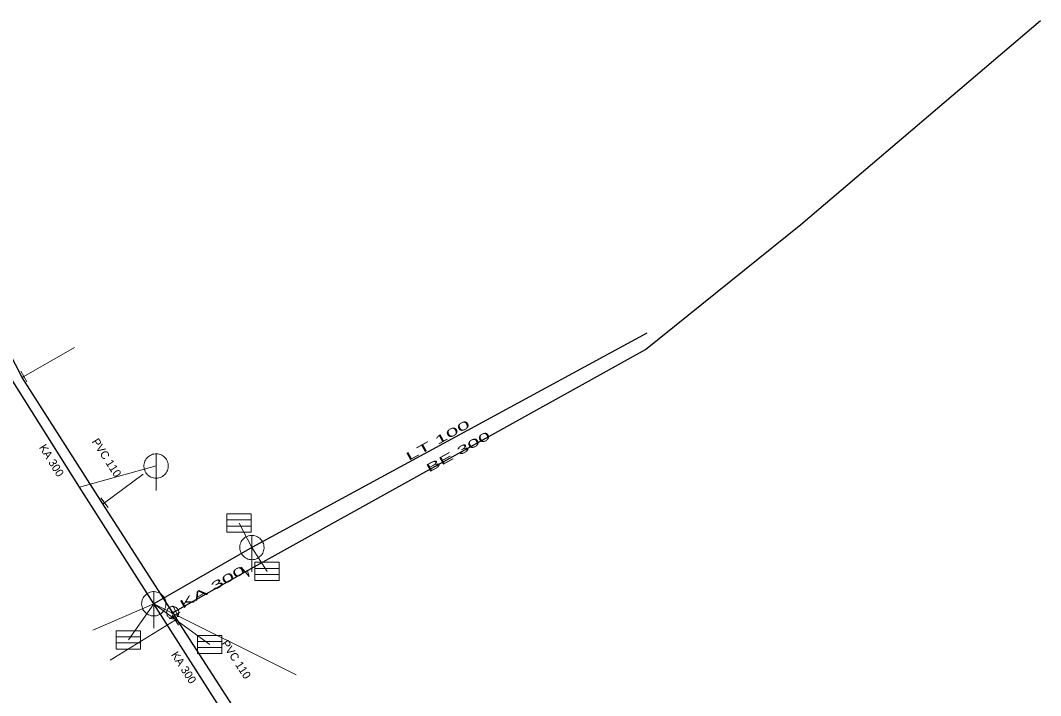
# Model space of a CAD drawing. Extents: x -688296 to -687852, y -973332 to -972816.
# Drawn here: x -687935.8 to -687852, y -973112.8 to -973057.3 of the extents above; entities that cross this region are included whole.
import ezdxf
from ezdxf.enums import TextEntityAlignment as Align

# ---------------------------------------------------------------- set-up
doc = ezdxf.new("R2010")
doc.units = 0
doc.header["$LTSCALE"] = 0.27
for name, color, linetype, lineweight in [('1', 7, 'Continuous', 25), ('11', 7, 'Continuous', 13), ('13', 7, 'Continuous', 13), ('14', 7, 'Continuous', 13), ('17', 7, 'Continuous', 25), ('22', 7, 'Continuous', 13), ('34', 7, 'Continuous', 13), ('47', 7, 'Continuous', 13)]:
    doc.layers.add(name, color=color, linetype=linetype, lineweight=lineweight)

msp = doc.modelspace()

# ---------------------------------------------------------------- linework, layer by layer
at = {"layer": '11'}
for p, q in [((-687924.64, -973093.94), (-687930.94, -973095.67)), ((-687917.83, -973098.63), (-687916.78, -973100.64)), ((-687915.53, -973102.61), (-687916.78, -973100.64)), ((-687929.84, -973107.42), (-687924.829, -973105.26)), ((-687926.92, -973108.23), (-687924.829, -973105.26)), ((-687920.239, -973108.609), (-687924.829, -973105.26)), ((-687913.14, -973111.1), (-687924.829, -973105.26))]:
    msp.add_line(p, q, dxfattribs=at)
at = {"layer": '13'}
for p, q in [((-687935.509, -973086.585), (-687931.329, -973084.21)), ((-687928.878, -973096.96), (-687925.69, -973094.62)), ((-687923.067, -973106.599), (-687928.399, -973109.899))]:
    msp.add_line(p, q, dxfattribs=at)
at = {"layer": '14', "lineweight": 25}
for p, q in [((-687884.357, -973083.031), (-687916.78, -973100.64)), ((-687916.78, -973100.64), (-687924.829, -973105.26)), ((-687916.609, -973118.16), (-687924.829, -973105.26))]:
    msp.add_line(p, q, dxfattribs=at)
at = {"layer": '14'}
for p, q in [((-687935.64, -973086.66), (-687935.509, -973086.585)), ((-687929, -973097.05), (-687928.878, -973096.96)), ((-687922.94, -973106.52), (-687923.067, -973106.599))]:
    msp.add_line(p, q, dxfattribs=at)
at = {"layer": '14', "lineweight": 25}
msp.add_lwpolyline([(-687924.829, -973105.26), (-687930.94, -973095.67), (-687938.239, -973084.09)], dxfattribs=at)
at = {"layer": '14'}
msp.add_lwpolyline([(-687923.129, -973106.219), (-687923.279, -973105.989), (-687923.039, -973105.87)], dxfattribs=at)
at = {"layer": '17'}
msp.add_line((-687923.039, -973105.87), (-687917.319, -973102.639), dxfattribs=at)
for points in [[(-687917.319, -973102.639), (-687884.48, -973084.37), (-687871.73, -973074.109), (-687852.039, -973057.339)], [(-687923.279, -973105.989), (-687929, -973097.05), (-687935.64, -973086.66), (-687936.739, -973084.53), (-687942.199, -973073.68), (-687943.129, -973071.829)], [(-687914.539, -973119.599), (-687915.43, -973118.17), (-687922.94, -973106.52), (-687923.129, -973106.219)]]:
    msp.add_lwpolyline(points, dxfattribs=at)
at = {"layer": '22'}
for p, q in [((-687924.64, -973095.94), (-687924.639, -973092.94)), ((-687918.841, -973098.373), (-687916.841, -973098.373)), ((-687918.841, -973098.873), (-687916.841, -973098.873)), ((-687916.78, -973102.64), (-687916.779, -973099.64)), ((-687916.541, -973102.353), (-687914.541, -973102.353)), ((-687916.541, -973102.853), (-687914.541, -973102.853)), ((-687924.829, -973107.26), (-687924.828, -973104.26)), ((-687927.931, -973107.973), (-687925.931, -973107.973)), ((-687927.931, -973108.473), (-687925.931, -973108.473)), ((-687921.25, -973108.352), (-687919.25, -973108.352)), ((-687921.25, -973108.852), (-687919.25, -973108.852))]:
    msp.add_line(p, q, dxfattribs=at)
for points in [[(-687923.64, -973093.94), (-687923.645, -973093.831), (-687923.663, -973093.723), (-687923.693, -973093.617), (-687923.733, -973093.516), (-687923.785, -973093.419), (-687923.847, -973093.329), (-687923.919, -973093.246), (-687923.999, -973093.172), (-687924.087, -973093.106), (-687924.181, -973093.051), (-687924.281, -973093.006), (-687924.386, -973092.973), (-687924.493, -973092.951), (-687924.602, -973092.941), (-687924.712, -973092.943), (-687924.82, -973092.957), (-687924.927, -973092.982), (-687925.03, -973093.019), (-687925.128, -973093.068), (-687925.22, -973093.126), (-687925.306, -973093.195), (-687925.383, -973093.272), (-687925.452, -973093.358), (-687925.511, -973093.45), (-687925.559, -973093.548), (-687925.596, -973093.651), (-687925.622, -973093.758), (-687925.636, -973093.866), (-687925.639, -973093.976), (-687925.629, -973094.085), (-687925.608, -973094.192), (-687925.574, -973094.296), (-687925.53, -973094.396), (-687925.475, -973094.491), (-687925.409, -973094.579), (-687925.335, -973094.659), (-687925.252, -973094.731), (-687925.162, -973094.793), (-687925.066, -973094.845), (-687924.964, -973094.886), (-687924.859, -973094.916), (-687924.751, -973094.934), (-687924.641, -973094.94), (-687924.532, -973094.934), (-687924.424, -973094.916), (-687924.319, -973094.887), (-687924.217, -973094.846), (-687924.12, -973094.794), (-687924.03, -973094.732), (-687923.947, -973094.661), (-687923.872, -973094.581), (-687923.807, -973094.493), (-687923.751, -973094.399), (-687923.707, -973094.299), (-687923.673, -973094.195), (-687923.651, -973094.087), (-687923.641, -973093.978)], [(-687918.841, -973097.873), (-687916.841, -973097.873), (-687916.841, -973099.373), (-687918.841, -973099.373)], [(-687915.78, -973100.64), (-687915.785, -973100.531), (-687915.803, -973100.423), (-687915.833, -973100.317), (-687915.873, -973100.216), (-687915.925, -973100.119), (-687915.987, -973100.029), (-687916.059, -973099.946), (-687916.139, -973099.872), (-687916.227, -973099.806), (-687916.321, -973099.751), (-687916.421, -973099.706), (-687916.526, -973099.673), (-687916.633, -973099.651), (-687916.742, -973099.641), (-687916.852, -973099.643), (-687916.96, -973099.657), (-687917.067, -973099.682), (-687917.17, -973099.719), (-687917.268, -973099.768), (-687917.36, -973099.826), (-687917.446, -973099.895), (-687917.523, -973099.972), (-687917.592, -973100.058), (-687917.651, -973100.15), (-687917.699, -973100.248), (-687917.736, -973100.351), (-687917.762, -973100.458), (-687917.776, -973100.566), (-687917.779, -973100.676), (-687917.769, -973100.785), (-687917.748, -973100.892), (-687917.714, -973100.996), (-687917.67, -973101.096), (-687917.615, -973101.191), (-687917.549, -973101.279), (-687917.475, -973101.359), (-687917.392, -973101.431), (-687917.302, -973101.493), (-687917.206, -973101.545), (-687917.104, -973101.586), (-687916.999, -973101.616), (-687916.891, -973101.634), (-687916.781, -973101.64), (-687916.672, -973101.634), (-687916.564, -973101.616), (-687916.459, -973101.587), (-687916.357, -973101.546), (-687916.26, -973101.494), (-687916.17, -973101.432), (-687916.087, -973101.361), (-687916.012, -973101.281), (-687915.947, -973101.193), (-687915.891, -973101.099), (-687915.847, -973100.999), (-687915.813, -973100.895), (-687915.791, -973100.787), (-687915.781, -973100.678)], [(-687916.541, -973101.853), (-687914.541, -973101.853), (-687914.541, -973103.353), (-687916.541, -973103.353)], [(-687923.829, -973105.26), (-687923.834, -973105.151), (-687923.852, -973105.043), (-687923.882, -973104.937), (-687923.922, -973104.836), (-687923.974, -973104.739), (-687924.036, -973104.649), (-687924.108, -973104.566), (-687924.188, -973104.492), (-687924.276, -973104.426), (-687924.37, -973104.371), (-687924.47, -973104.326), (-687924.575, -973104.293), (-687924.682, -973104.271), (-687924.791, -973104.261), (-687924.901, -973104.263), (-687925.009, -973104.277), (-687925.116, -973104.302), (-687925.219, -973104.339), (-687925.317, -973104.388), (-687925.409, -973104.446), (-687925.495, -973104.515), (-687925.572, -973104.592), (-687925.641, -973104.678), (-687925.7, -973104.77), (-687925.748, -973104.868), (-687925.785, -973104.971), (-687925.811, -973105.078), (-687925.825, -973105.186), (-687925.828, -973105.296), (-687925.818, -973105.405), (-687925.797, -973105.512), (-687925.763, -973105.616), (-687925.719, -973105.716), (-687925.664, -973105.811), (-687925.598, -973105.899), (-687925.524, -973105.979), (-687925.441, -973106.051), (-687925.351, -973106.113), (-687925.255, -973106.165), (-687925.153, -973106.206), (-687925.048, -973106.236), (-687924.94, -973106.254), (-687924.83, -973106.26), (-687924.721, -973106.254), (-687924.613, -973106.236), (-687924.508, -973106.207), (-687924.406, -973106.166), (-687924.309, -973106.114), (-687924.219, -973106.052), (-687924.136, -973105.981), (-687924.061, -973105.901), (-687923.996, -973105.813), (-687923.94, -973105.719), (-687923.896, -973105.619), (-687923.862, -973105.515), (-687923.84, -973105.407), (-687923.83, -973105.298)], [(-687927.931, -973107.473), (-687925.931, -973107.473), (-687925.931, -973108.973), (-687927.931, -973108.973)], [(-687921.25, -973107.852), (-687919.25, -973107.852), (-687919.25, -973109.352), (-687921.25, -973109.352)]]:
    msp.add_lwpolyline(points, close=True, dxfattribs=at)
at = {"layer": '34'}
for p, q in [((-687935.756, -973086.15), (-687935.262, -973087.019)), ((-687929.174, -973096.557), (-687928.582, -973097.363)), ((-687922.706, -973105.951), (-687923.551, -973106.486)), ((-687923.263, -973105.423), (-687922.815, -973106.317)), ((-687923.33, -973106.174), (-687922.804, -973107.024))]:
    msp.add_line(p, q, dxfattribs=at)
at = {"layer": '47'}
msp.add_line((-687917.647, -973102.249), (-687917.494, -973102.736), dxfattribs=at)
msp.add_lwpolyline([(-687917.647, -973102.249), (-687916.99, -973103.028), (-687917.143, -973102.541)], dxfattribs=at)
for points in [[(-687923.009, -973106.41), (-687922.967, -973106.379), (-687922.927, -973106.344), (-687922.893, -973106.306), (-687922.861, -973106.264), (-687922.835, -973106.218), (-687922.813, -973106.17), (-687922.797, -973106.121), (-687922.786, -973106.07), (-687922.78, -973106.018), (-687922.779, -973105.966), (-687922.784, -973105.913), (-687922.795, -973105.862), (-687922.811, -973105.813), (-687922.832, -973105.764), (-687922.857, -973105.719), (-687922.888, -973105.677), (-687922.923, -973105.637), (-687922.962, -973105.602), (-687923.003, -973105.571), (-687923.049, -973105.545), (-687923.097, -973105.523), (-687923.147, -973105.506), (-687923.198, -973105.495), (-687923.249, -973105.489), (-687923.301, -973105.489), (-687923.354, -973105.494), (-687923.405, -973105.505), (-687923.454, -973105.521), (-687923.503, -973105.542), (-687923.548, -973105.567), (-687923.59, -973105.598), (-687923.63, -973105.633), (-687923.666, -973105.671), (-687923.696, -973105.713), (-687923.722, -973105.759), (-687923.744, -973105.806), (-687923.761, -973105.856), (-687923.772, -973105.907), (-687923.778, -973105.959), (-687923.778, -973106.011), (-687923.773, -973106.064), (-687923.763, -973106.114), (-687923.746, -973106.164), (-687923.725, -973106.213), (-687923.7, -973106.258), (-687923.669, -973106.3), (-687923.634, -973106.34), (-687923.596, -973106.375), (-687923.554, -973106.406), (-687923.508, -973106.432), (-687923.461, -973106.454), (-687923.412, -973106.47), (-687923.361, -973106.482), (-687923.308, -973106.487), (-687923.256, -973106.488), (-687923.203, -973106.483), (-687923.153, -973106.472), (-687923.103, -973106.456), (-687923.054, -973106.435)], [(-687923.234, -973106.058), (-687923.227, -973106.053), (-687923.221, -973106.047), (-687923.215, -973106.041), (-687923.21, -973106.034), (-687923.206, -973106.026), (-687923.202, -973106.018), (-687923.199, -973106.01), (-687923.197, -973106.002), (-687923.197, -973105.993), (-687923.197, -973105.985), (-687923.198, -973105.976), (-687923.199, -973105.968), (-687923.202, -973105.96), (-687923.205, -973105.952), (-687923.209, -973105.944), (-687923.214, -973105.937), (-687923.22, -973105.931), (-687923.226, -973105.925), (-687923.233, -973105.92), (-687923.241, -973105.916), (-687923.249, -973105.912), (-687923.257, -973105.909), (-687923.265, -973105.907), (-687923.274, -973105.906), (-687923.282, -973105.907), (-687923.291, -973105.908), (-687923.299, -973105.909), (-687923.307, -973105.912), (-687923.315, -973105.915), (-687923.323, -973105.919), (-687923.33, -973105.924), (-687923.336, -973105.93), (-687923.342, -973105.936), (-687923.347, -973105.943), (-687923.351, -973105.951), (-687923.355, -973105.958), (-687923.358, -973105.967), (-687923.36, -973105.975), (-687923.361, -973105.984), (-687923.36, -973105.992), (-687923.359, -973106.001), (-687923.358, -973106.009), (-687923.355, -973106.017), (-687923.352, -973106.025), (-687923.348, -973106.033), (-687923.343, -973106.04), (-687923.337, -973106.046), (-687923.331, -973106.052), (-687923.324, -973106.057), (-687923.316, -973106.061), (-687923.309, -973106.065), (-687923.3, -973106.068), (-687923.292, -973106.07), (-687923.283, -973106.07), (-687923.275, -973106.07), (-687923.266, -973106.069), (-687923.258, -973106.068), (-687923.25, -973106.065), (-687923.242, -973106.062)]]:
    msp.add_lwpolyline(points, close=True, dxfattribs=at)

# ---------------------------------------------------------------- texts
at = {"layer": '1'}
for s, rotation, width, p in [('LT 100', 29, 2.1, (-687901.3596, -973092.1187)), ('LT 100', 29, 2.1, (-687901.3596, -973092.1187)), ('LT 100', 29, 2.1, (-687901.3596, -973092.1187)), ('LT 100', 29, 2.1, (-687901.3596, -973092.1187)), ('LT 100', 29, 2.1, (-687901.3596, -973092.1187)), ('BE 300', 29, 2, (-687899.6876, -973093.0657)), ('BE 300', 29, 2, (-687899.6876, -973093.0657)), ('BE 300', 29, 2, (-687899.6876, -973093.0657)), ('BE 300', 29, 2, (-687899.6876, -973093.0657)), ('BE 300', 29, 2, (-687899.6876, -973093.0657)), ('KA 300', 30, 2.05, (-687919.8677, -973104.1741)), ('KA 300', 30, 2.05, (-687919.8677, -973104.1741)), ('KA 300', 30, 2.05, (-687919.8677, -973104.1741)), ('KA 300', 30, 2.05, (-687919.8677, -973104.1741)), ('KA 300', 30, 2.05, (-687919.8677, -973104.1741))]:
    msp.add_text(s, height=0.6667, rotation=rotation, dxfattribs=dict(at, width=width)).set_placement(p, align=Align.CENTER)
for s, rotation, p in [('PVC 110 ', 303, (-687928.913, -973093.5425)), ('PVC 110 ', 303, (-687928.913, -973093.5425)), ('PVC 110 ', 303, (-687928.913, -973093.5425)), ('PVC 110 ', 303, (-687928.913, -973093.5425)), ('PVC 110 ', 303, (-687928.913, -973093.5425)), ('KA 300', 302, (-687933.5052, -973093.6616)), ('KA 300', 302, (-687933.5052, -973093.6616)), ('KA 300', 302, (-687933.5052, -973093.6616)), ('KA 300', 302, (-687933.5052, -973093.6616)), ('KA 300', 302, (-687933.5052, -973093.6616)), ('PVC 110 ', 303, (-687918.275, -973110.1165)), ('PVC 110 ', 303, (-687918.275, -973110.1165)), ('PVC 110 ', 303, (-687918.275, -973110.1165)), ('PVC 110 ', 303, (-687918.275, -973110.1165)), ('PVC 110 ', 303, (-687918.275, -973110.1165)), ('KA 300', 303, (-687922.6476, -973110.6748)), ('KA 300', 303, (-687922.6476, -973110.6748)), ('KA 300', 303, (-687922.6476, -973110.6748)), ('KA 300', 303, (-687922.6476, -973110.6748)), ('KA 300', 303, (-687922.6476, -973110.6748))]:
    msp.add_text(s, height=0.6667, rotation=rotation, dxfattribs=at).set_placement(p, align=Align.CENTER)

doc.saveas('drawing.dxf')
